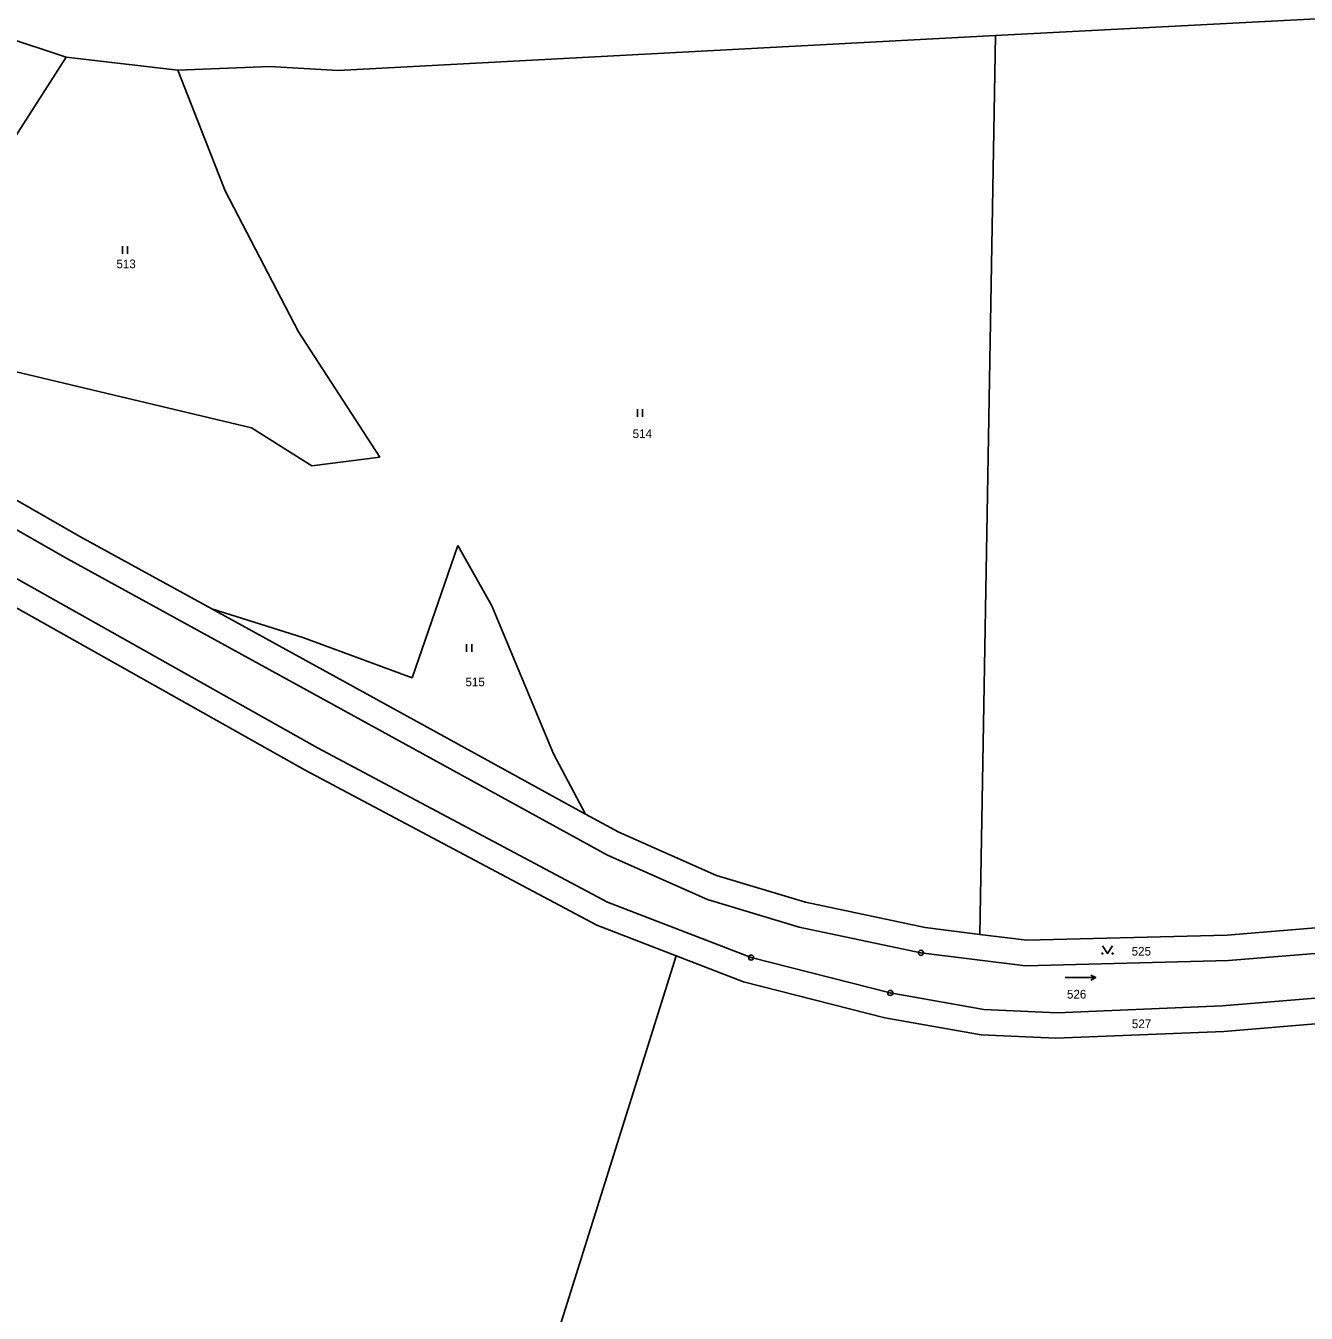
# Model space of a CAD drawing. Extents: x -759947 to -757003, y -1019641 to -1017100.
# Drawn here: x -757821 to -757569.9, y -1019281.8 to -1019029.4 of the extents above; entities that cross this region are included whole.
import ezdxf

# ---------------------------------------------------------------- set-up
doc = ezdxf.new("R2010")
doc.units = 0
doc.header["$LTSCALE"] = 0.68
for name, color, linetype, lineweight in [('1', 7, 'Continuous', 25), ('3', 7, 'Continuous', 25), ('8', 7, 'Continuous', 25)]:
    doc.layers.add(name, color=color, linetype=linetype, lineweight=lineweight)
doc.layers.add('2', color=7, linetype='Continuous')

msp = doc.modelspace()

# ---------------------------------------------------------------- linework, layer by layer
at = {"layer": '1'}
for p, q in [((-757630.83, -1019031.38), (-757488.89, -1019023.89)), ((-757825.26, -1019031.52), (-757813.04, -1019035.6)), ((-757759.73, -1019038.19), (-757630.83, -1019031.38)), ((-757633.96, -1019207.57), (-757630.83, -1019031.38)), ((-757813.04, -1019035.6), (-757831.29, -1019064.07)), ((-757791.11, -1019038.15), (-757813.04, -1019035.6)), ((-757791.11, -1019038.15), (-757773.09, -1019037.42)), ((-757781.88, -1019061.79), (-757791.11, -1019038.15)), ((-757773.09, -1019037.42), (-757759.73, -1019038.19)), ((-757767.49, -1019089.45), (-757781.88, -1019061.79)), ((-757810.34, -1019129.59), (-757890.77, -1019083.52)), ((-757891.09, -1019089.05), (-757812.79, -1019133.95)), ((-757751.55, -1019114), (-757767.49, -1019089.45)), ((-757824.44, -1019096.92), (-757776.68, -1019108.28)), ((-757776.68, -1019108.28), (-757764.88, -1019115.72)), ((-757764.88, -1019115.72), (-757751.55, -1019114)), ((-757784.5, -1019143.77), (-757810.34, -1019129.59)), ((-757736.24, -1019131.31), (-757745.19, -1019157.24)), ((-757729.56, -1019143.16), (-757736.24, -1019131.31)), ((-757763.77, -1019170.96), (-757828.94, -1019134.35)), ((-757812.79, -1019133.95), (-757706.92, -1019192.04)), ((-757831.34, -1019138.74), (-757766.17, -1019175.35)), ((-757784.5, -1019143.77), (-757766.66, -1019149.33)), ((-757711.23, -1019183.97), (-757784.5, -1019143.77)), ((-757717.53, -1019172.17), (-757729.56, -1019143.16)), ((-757745.19, -1019157.24), (-757766.66, -1019149.33)), ((-757706.92, -1019201.21), (-757763.77, -1019170.96)), ((-757711.23, -1019183.97), (-757717.53, -1019172.17)), ((-757709, -1019205.77), (-757766.17, -1019175.35)), ((-757704.7, -1019187.55), (-757711.23, -1019183.97)), ((-757685.55, -1019196.03), (-757704.7, -1019187.55)), ((-757706.92, -1019192.04), (-757687.29, -1019200.73)), ((-757668.08, -1019201.27), (-757685.55, -1019196.03)), ((-757687.29, -1019200.73), (-757669.32, -1019206.12)), ((-757481.46, -1019199.17), (-757585.44, -1019207.69)), ((-757678.78, -1019212.1), (-757706.92, -1019201.21)), ((-757644.65, -1019206.24), (-757668.08, -1019201.27)), ((-757693.45, -1019211.78), (-757709, -1019205.77)), ((-757585.17, -1019212.69), (-757481.11, -1019204.16)), ((-757669.32, -1019206.12), (-757645.48, -1019211.17)), ((-757633.96, -1019207.57), (-757644.65, -1019206.24)), ((-757624.72, -1019208.72), (-757633.96, -1019207.57)), ((-757585.44, -1019207.69), (-757624.72, -1019208.72)), ((-757442.32, -1019209.75), (-757586.4, -1019221.58)), ((-757693.45, -1019211.78), (-757730.18, -1019328.81)), ((-757680.27, -1019216.88), (-757693.45, -1019211.78)), ((-757651.48, -1019219.04), (-757678.78, -1019212.1)), ((-757645.48, -1019211.17), (-757624.97, -1019213.73)), ((-757624.97, -1019213.73), (-757585.17, -1019212.69)), ((-757586.12, -1019226.57), (-757441.93, -1019214.74)), ((-757652.53, -1019223.93), (-757680.27, -1019216.88)), ((-757633.12, -1019222.28), (-757651.48, -1019219.04)), ((-757618.8, -1019222.94), (-757633.12, -1019222.28)), ((-757586.4, -1019221.58), (-757618.8, -1019222.94)), ((-757633.67, -1019227.26), (-757652.53, -1019223.93)), ((-757633.67, -1019227.26), (-757619.03, -1019227.93)), ((-757619.03, -1019227.93), (-757586.12, -1019226.57))]:
    msp.add_line(p, q, dxfattribs=at)
at = {"layer": '3'}
for p, q in [((-757802.001, -1019074.13), (-757802.001, -1019072.63)), ((-757801, -1019074.13), (-757801, -1019072.63)), ((-757701.061, -1019106.08), (-757701.061, -1019104.58)), ((-757700.06, -1019106.08), (-757700.06, -1019104.58)), ((-757734.531, -1019152.19), (-757734.531, -1019150.69)), ((-757733.53, -1019152.19), (-757733.53, -1019150.69)), ((-757611.203, -1019216.039), (-757612.18, -1019216.54))]:
    msp.add_line(p, q, dxfattribs=at)
for points in [[(-757609.9, -1019209.809), (-757608.9, -1019211.31), (-757607.9, -1019209.809)], [(-757617.203, -1019216.039), (-757611.203, -1019216.039), (-757612.18, -1019215.537)]]:
    msp.add_lwpolyline(points, dxfattribs=at)
for centre in [(-757609.9, -1019211.3095), (-757607.9, -1019211.3095)]:
    msp.add_circle(centre, 0.1, dxfattribs=at)
at = {"layer": '8'}
for centre, radius in [((-757645.48, -1019211.1699), 0.5), ((-757678.78, -1019212.0999), 0.5), ((-757678.78, -1019212.0999), 0.0303), ((-757645.48, -1019211.1699), 0.0303), ((-757651.48, -1019219.0399), 0.5), ((-757651.48, -1019219.0399), 0.0303)]:
    msp.add_circle(centre, radius, dxfattribs=at)

# ---------------------------------------------------------------- texts
at = {"layer": '2'}
for s, p in [('513', (-757803.18, -1019076.975)), ('514', (-757701.99, -1019110.265)), ('515', (-757734.76, -1019158.915)), ('525', (-757604.17, -1019211.715)), ('526', (-757616.85, -1019220.135)), ('527', (-757604.13, -1019225.935))]:
    msp.add_text(s, height=1.7, dxfattribs=at).set_placement(p)

doc.saveas('drawing.dxf')
